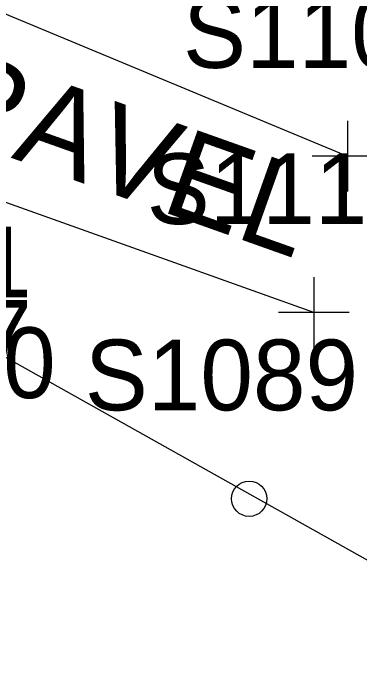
# Model space of a CAD drawing. Extents: x 816928 to 825690, y 436959 to 448212.
# Drawn here: x 819061.84 to 819081.48, y 445201.32 to 445238.31 of the extents above; entities that cross this region are included whole.
import ezdxf

# ---------------------------------------------------------------- set-up
doc = ezdxf.new("R2010")
doc.units = 0
for name, color, linetype in [('SURVEY - DTM - Breaklines - Points - Numbers', 7, 'Continuous'), ('SURVEY - DTM - Spot Points - Locators', 7, 'Continuous'), ('SURVEY - DTM - Spot Points - Point Numbers', 7, 'Continuous'), ('SURVEY - PROPERTY - ROW Lines Text', 7, 'Continuous'), ('SURVEY - TRANSPORTATION - Features', 7, 'Continuous'), ('SURVEY - TRANSPORTATION - Features - Points - Locators', 7, 'Continuous'), ('SURVEY - TRANSPORTATION - Features - Points - Numbers', 7, 'Continuous'), ('SURVEY - TRANSPORTATION - Features Text', 7, 'Continuous')]:
    doc.layers.add(name, color=color, linetype=linetype)

msp = doc.modelspace()

# ---------------------------------------------------------------- linework, layer by layer
at = {"layer": 'SURVEY - DTM - Spot Points - Locators'}
msp.add_circle((819075.209, 445210.839), 1, dxfattribs=at)
at = {"layer": 'SURVEY - PROPERTY - ROW Lines Text'}
msp.add_lwpolyline([(819092.658, 445201.321), (819038.605, 445231.609)], dxfattribs=at)
at = {"layer": 'SURVEY - TRANSPORTATION - Features'}
for points in [[(819039.074, 445258.681), (819046.196, 445244.609), (819080.768, 445230.212)], [(819078.871, 445221.378), (819040.191, 445235.179), (819026.695, 445241.322)]]:
    msp.add_lwpolyline(points, dxfattribs=at)
at = {"layer": 'SURVEY - TRANSPORTATION - Features - Points - Locators'}
for p, q in [((819080.768, 445232.212), (819080.768, 445228.212)), ((819082.768, 445230.212), (819078.768, 445230.212)), ((819078.871, 445223.378), (819078.871, 445219.378)), ((819080.871, 445221.378), (819076.871, 445221.378))]:
    msp.add_line(p, q, dxfattribs=at)

# ---------------------------------------------------------------- texts
at = {"layer": 'SURVEY - DTM - Breaklines - Points - Numbers'}
for s, p in [('S951', (819050.398, 445222.227)), ('S957', (819050.419, 445218.083)), ('S950', (819051.767, 445216.531))]:
    msp.add_text(s, height=4, dxfattribs=at).set_placement(p)
at = {"layer": 'SURVEY - DTM - Spot Points - Point Numbers'}
msp.add_text('S1089', height=4, dxfattribs=at).set_placement((819065.906, 445215.839))
at = {"layer": 'SURVEY - TRANSPORTATION - Features - Points - Numbers'}
for s, p in [('S1109', (819071.465, 445235.212)), ('S1110', (819069.41, 445226.378))]:
    msp.add_text(s, height=4, dxfattribs=at).set_placement(p)
at = {"layer": 'SURVEY - TRANSPORTATION - Features Text'}
msp.add_text('GRAVEL', height=5, rotation=340.4515, dxfattribs=at).set_placement((819052.242, 445233.494))

doc.saveas('drawing.dxf')
